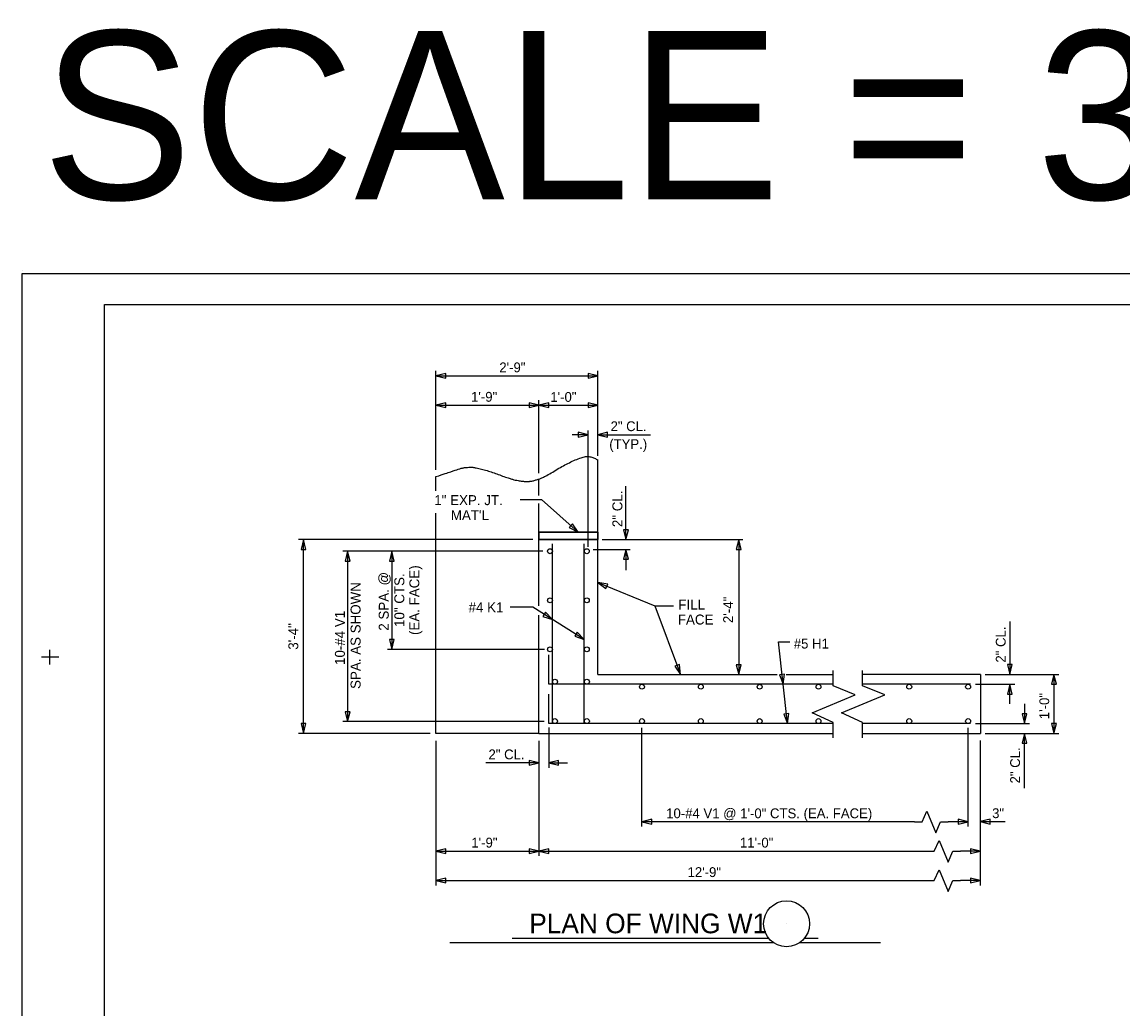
# Model space of a CAD drawing. Extents: x -41 to 251, y -169 to 237.
# Drawn here: x 0 to 18.71, y -82.14 to -65.38 of the extents above; entities that cross this region are included whole.
import ezdxf

# ---------------------------------------------------------------- set-up
doc = ezdxf.new("R2010")
doc.units = 0
for name, color, linetype in [('Arrowhead Terminators CELL', 7, 'Continuous'), ('Beam Bolsters CELL', 7, 'Continuous'), ('Default', 7, 'Continuous'), ('Dimension Lines', 7, 'Continuous'), ('Mis Object Lines', 7, 'Continuous'), ('Plan Sheet CELL', 7, 'Continuous'), ('Plot Shape CELL', 7, 'Continuous'), ('Rebar K Bar Lines', 7, 'Continuous'), ('Rebar Lines', 7, 'Continuous'), ('Sub End Bent Cap Lines CELL', 7, 'Continuous'), ('Text', 7, 'Continuous'), ('Title Text', 7, 'Continuous'), ('User Information Notes CELL', 7, 'Continuous')]:
    doc.layers.add(name, color=color, linetype=linetype)

# ---------------------------------------------------------------- blocks, each defined once
blk = doc.blocks.new('AH')
at = {"layer": 'Sub End Bent Cap Lines CELL'}
blk.add_lwpolyline([(0, 0), (-1.25, 0.31), (-1.25, -0.31)], close=True, dxfattribs=at)

msp = doc.modelspace()

# ---------------------------------------------------------------- linework, layer by layer
at = {"layer": 'Arrowhead Terminators CELL'}
for points in [[(7.033, -71.387), (7.2, -71.428), (7.2, -71.345)], [(9.783, -71.387), (9.617, -71.345), (9.617, -71.428)], [(7.033, -71.887), (7.2, -71.928), (7.2, -71.845)], [(8.783, -71.887), (8.617, -71.845), (8.617, -71.928)], [(8.783, -71.887), (8.95, -71.928), (8.95, -71.845)], [(9.783, -71.887), (9.617, -71.845), (9.617, -71.928)], [(9.617, -72.387), (9.45, -72.345), (9.45, -72.428)], [(9.783, -72.387), (9.95, -72.428), (9.95, -72.345)], [(9.45, -74.044), (9.354, -73.903), (9.298, -73.965)], [(10.261, -74.169), (10.302, -74.003), (10.219, -74.003)], [(4.783, -74.169), (4.742, -74.336), (4.825, -74.336)], [(12.178, -74.169), (12.136, -74.336), (12.219, -74.336)], [(5.533, -74.367), (5.492, -74.534), (5.575, -74.534)], [(6.283, -74.367), (6.242, -74.534), (6.325, -74.534)], [(10.261, -74.337), (10.219, -74.504), (10.302, -74.504)], [(9.783, -74.901), (9.922, -75.002), (9.953, -74.925)], [(9.013, -75.527), (8.893, -75.404), (8.849, -75.475)], [(9.554, -75.864), (9.435, -75.741), (9.391, -75.811)], [(6.283, -76.034), (6.325, -75.867), (6.242, -75.867)], [(11.19, -76.461), (11.17, -76.291), (11.093, -76.32)], [(12.178, -76.461), (12.219, -76.295), (12.136, -76.295)], [(12.932, -76.628), (12.955, -76.458), (12.872, -76.467)], [(5.533, -77.261), (5.575, -77.095), (5.492, -77.095)], [(13.004, -77.294), (13.028, -77.125), (12.945, -77.134)], [(4.783, -77.462), (4.825, -77.296), (4.742, -77.296)], [(8.783, -77.961), (8.617, -77.92), (8.617, -78.003)], [(8.95, -77.961), (9.116, -78.003), (9.116, -77.92)], [(10.533, -78.963), (10.7, -79.004), (10.7, -78.921)], [(16.075, -78.963), (15.908, -78.921), (15.908, -79.004)], [(16.282, -78.961), (16.448, -79.003), (16.448, -78.92)], [(7.033, -79.461), (7.2, -79.503), (7.2, -79.42)], [(8.783, -79.461), (8.617, -79.42), (8.617, -79.503)], [(8.783, -79.461), (8.95, -79.503), (8.95, -79.42)], [(16.282, -79.461), (16.116, -79.42), (16.116, -79.503)], [(7.033, -79.961), (7.2, -80.003), (7.2, -79.92)], [(16.282, -79.961), (16.116, -79.92), (16.116, -80.003)]]:
    msp.add_lwpolyline(points, close=True, dxfattribs=at)
at = {"layer": 'Beam Bolsters CELL'}
msp.add_lwpolyline([(9.742, -74.044), (9.742, -74.044), (9.742, -74.044), (9.742, -74.044), (9.742, -74.044), (9.742, -74.044)], dxfattribs=at)
at = {"layer": 'Default'}
for points in [[(13.781, -77.536), (13.781, -77.278), (13.424, -77.114), (14.156, -76.808), (13.781, -76.653), (13.781, -76.391)], [(14.283, -77.536), (14.283, -77.278), (13.926, -77.114), (14.658, -76.808), (14.283, -76.653), (14.283, -76.391)], [(15.165, -78.963), (15.294, -78.963), (15.376, -78.784), (15.529, -79.15), (15.606, -78.963), (15.738, -78.963)], [(15.372, -79.461), (15.501, -79.461), (15.583, -79.282), (15.736, -79.649), (15.814, -79.461), (15.945, -79.461)], [(15.372, -79.961), (15.501, -79.961), (15.583, -79.782), (15.736, -80.149), (15.814, -79.961), (15.945, -79.961)]]:
    msp.add_lwpolyline(points, dxfattribs=at)
at = {"layer": 'Dimension Lines'}
for p, q in [((10.261, -74.169), (10.261, -73.26)), ((8.465, -73.487), (8.825, -73.487)), ((8.825, -73.487), (9.45, -74.044)), ((9.785, -74.044), (9.45, -74.044)), ((9.783, -74.044), (9.783, -74.169)), ((9.783, -74.169), (9.785, -74.044)), ((8.677, -74.169), (4.699, -74.169)), ((4.783, -77.462), (4.783, -74.169)), ((9.855, -74.169), (12.25, -74.169)), ((12.178, -74.169), (12.178, -76.461)), ((8.847, -74.367), (5.449, -74.367)), ((5.533, -74.367), (5.533, -77.261)), ((6.283, -74.367), (6.283, -76.034)), ((9.707, -74.337), (10.333, -74.337)), ((10.261, -74.337), (10.261, -74.687)), ((9.783, -74.901), (10.754, -75.294)), ((10.754, -75.294), (11.19, -76.461)), ((10.754, -75.294), (11.069, -75.294)), ((16.783, -75.562), (16.783, -76.461)), ((8.878, -76.034), (6.21, -76.034)), ((16.367, -76.461), (17.617, -76.461)), ((16.367, -76.461), (16.72, -76.461)), ((17.533, -76.461), (17.533, -77.461)), ((16.2, -76.628), (16.867, -76.628)), ((16.783, -76.962), (16.783, -76.628)), ((17.033, -76.96), (17.033, -77.294)), ((8.871, -77.261), (5.449, -77.261)), ((8.95, -77.36), (8.95, -78.044)), ((10.533, -79.046), (10.533, -77.365)), ((16.075, -79.046), (16.075, -77.365)), ((16.2, -77.294), (17.117, -77.294)), ((6.933, -77.461), (4.699, -77.461)), ((7.033, -77.589), (7.033, -80.044)), ((8.783, -77.589), (8.783, -79.544)), ((16.282, -77.58), (16.282, -80.044)), ((16.367, -77.461), (17.617, -77.461)), ((16.367, -77.461), (17.009, -77.461)), ((17.033, -78.394), (17.033, -77.461)), ((8.783, -77.961), (7.883, -77.961)), ((8.95, -77.961), (9.269, -77.961)), ((15.165, -78.963), (10.533, -78.963)), ((16.075, -78.963), (15.738, -78.963)), ((16.282, -78.961), (16.707, -78.961)), ((7.033, -79.461), (8.783, -79.461)), ((8.783, -79.461), (15.372, -79.461)), ((16.282, -79.461), (15.945, -79.461)), ((7.033, -79.961), (15.372, -79.961)), ((16.282, -79.961), (15.945, -79.961))]:
    msp.add_line(p, q, dxfattribs=at)
msp.add_lwpolyline([(9.785, -74.044), (9.783, -74.169), (8.783, -74.169), (8.783, -74.044)], close=True, dxfattribs=at)
for points in [[(9.45, -74.044), (8.783, -74.044), (8.783, -74.169), (9.783, -74.169)], [(9.783, -74.169), (9.785, -74.044), (9.783, -74.044)], [(9.554, -75.864), (8.677, -75.319), (8.295, -75.319)], [(13.004, -77.294), (12.854, -75.908), (13.046, -75.908)]]:
    msp.add_lwpolyline(points, dxfattribs=at)
at = {"layer": 'Mis Object Lines'}
for p, q in [((9.783, -76.461), (9.783, -72.817)), ((7.033, -73.343), (7.033, -73.099)), ((8.783, -73.42), (8.783, -73.139)), ((8.783, -75.296), (8.783, -73.555)), ((7.033, -77.461), (7.033, -73.722)), ((9.783, -74.169), (8.783, -74.169)), ((8.783, -77.461), (8.783, -75.452)), ((9.783, -76.461), (12.828, -76.461)), ((12.983, -76.461), (13.781, -76.461)), ((16.283, -76.461), (14.283, -76.461)), ((8.783, -77.461), (7.033, -77.461)), ((8.783, -77.461), (13.781, -77.461)), ((14.283, -77.461), (16.283, -77.461))]:
    msp.add_line(p, q, dxfattribs=at)
msp.add_lwpolyline([(16.283, -76.461), (16.283, -77.461)], dxfattribs=at)
msp.add_open_spline([(7.033, -73.099), (7.165, -73.056), (7.296, -73.012), (7.428, -72.969), (7.45, -72.961), (7.473, -72.956), (7.497, -72.951), (7.52, -72.946), (7.544, -72.944), (7.567, -72.943), (7.614, -72.94), (7.662, -72.94), (7.709, -72.95), (7.807, -72.97), (7.901, -72.997), (7.996, -73.028), (8.093, -73.06), (8.188, -73.1), (8.285, -73.13), (8.333, -73.145), (8.381, -73.158), (8.43, -73.167), (8.465, -73.174), (8.501, -73.178), (8.537, -73.181), (8.549, -73.182), (8.561, -73.182), (8.573, -73.182), (8.585, -73.182), (8.598, -73.182), (8.611, -73.181), (8.624, -73.18), (8.637, -73.178), (8.65, -73.176), (8.677, -73.172), (8.703, -73.166), (8.728, -73.158), (8.783, -73.141), (8.835, -73.12), (8.886, -73.094), (8.994, -73.04), (9.094, -72.972), (9.201, -72.915), (9.299, -72.862), (9.4, -72.815), (9.504, -72.778), (9.57, -72.754), (9.65, -72.757), (9.716, -72.783), (9.74, -72.793), (9.762, -72.803), (9.783, -72.817)], degree=3, dxfattribs=at)
at = {"layer": 'Plan Sheet CELL'}
for p, q in [((0, -69.65), (0, -69.65)), ((1.402, -70.174), (43.962, -70.174)), ((1.402, -98.104), (1.402, -70.174)), ((0.475, -76.292), (0.475, -76.04)), ((0.333, -76.159), (0.626, -76.159))]:
    msp.add_line(p, q, dxfattribs=at)
at = {"layer": 'Plot Shape CELL'}
msp.add_lwpolyline([(0, -69.65), (43.974, -69.65), (43.974, -98.91), (0, -98.91)], close=True, dxfattribs=at)
at = {"layer": 'Rebar K Bar Lines'}
for p, q in [((9.013, -77.294), (9.013, -74.243)), ((9.554, -77.294), (9.554, -74.243))]:
    msp.add_line(p, q, dxfattribs=at)
at = {"layer": 'Rebar Lines'}
for p, q in [((8.95, -76.628), (8.95, -76.128)), ((13.781, -76.628), (8.95, -76.628)), ((16.115, -76.628), (14.283, -76.628)), ((8.95, -77.294), (8.95, -76.794)), ((13.781, -77.294), (8.95, -77.294)), ((16.115, -77.294), (14.283, -77.294))]:
    msp.add_line(p, q, dxfattribs=at)
for centre in [(8.971, -74.367), (9.596, -74.367), (8.971, -75.201), (9.596, -75.201), (8.971, -76.034), (9.596, -76.034), (9.055, -76.584), (9.598, -76.584), (10.533, -76.669), (11.533, -76.669), (12.533, -76.669), (13.533, -76.669), (15.075, -76.669), (16.075, -76.669), (9.055, -77.253), (9.598, -77.253), (10.533, -77.253), (11.533, -77.253), (12.533, -77.253), (13.533, -77.253), (15.075, -77.253), (16.075, -77.253)]:
    msp.add_circle(centre, 0.0417, dxfattribs=at)
at = {"layer": 'Text'}
for p, q in [((7.033, -72.986), (7.033, -71.303)), ((7.033, -71.387), (9.783, -71.387)), ((9.783, -72.745), (9.783, -71.303)), ((8.783, -73.043), (8.783, -71.803)), ((7.033, -71.887), (8.783, -71.887)), ((8.783, -71.887), (9.783, -71.887)), ((9.617, -72.387), (9.346, -72.387)), ((9.617, -74.295), (9.617, -72.314)), ((9.783, -72.387), (10.676, -72.387))]:
    msp.add_line(p, q, dxfattribs=at)
at = {"layer": 'Title Text'}
for p, q in [((8.33, -80.941), (12.687, -80.941)), ((13.294, -80.941), (13.526, -80.941)), ((7.268, -81.015), (12.766, -81.015)), ((13.215, -81.015), (14.588, -81.015))]:
    msp.add_line(p, q, dxfattribs=at)
for centre, radius in [((12.99, -80.696), 0.39), ((12.996, -80.69), 0.000000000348)]:
    msp.add_circle(centre, radius, dxfattribs=at)
at = {"layer": 'User Information Notes CELL'}
for p, q in [((0, -69.599), (0, -69.599)), ((1.402, -70.174), (1.402, -70.174))]:
    msp.add_line(p, q, dxfattribs=at)

# ---------------------------------------------------------------- block references
at = {"layer": 'Arrowhead Terminators CELL', "xscale": 0.1336, "yscale": 0.1336}
for p, rotation in [((16.783, -76.461), -90), ((17.533, -76.461), 90), ((16.783, -76.628), 90), ((17.033, -77.294), -90), ((17.533, -77.461), -90), ((17.033, -77.461), 90)]:
    msp.add_blockref('AH', p, dxfattribs=dict(at, rotation=rotation))

# ---------------------------------------------------------------- texts
at = {"layer": 'Text'}
for s, height, p in [('SCALE = 3/4"', 2.86, (0.339, -68.389)), ('2\'-9"', 0.1667, (8.11, -71.327)), ('1\'-9"', 0.1667, (7.63, -71.827)), ('1\'-0"', 0.1667, (8.977, -71.83)), ('2" CL.', 0.1667, (10, -72.327))]:
    msp.add_text(s, height=height, dxfattribs=at).set_placement(p)
for s, height, rotation, p in [('(TYP.)', 0.1667, 360, (9.978, -72.63)), ('1" EXP. JT.', 0.16954, 360, (7.005, -73.584)), ('2" CL.', 0.1695, 90, (10.201, -73.957)), ("MAT'L", 0.1695, 360, (7.286, -73.839)), ('(EA. FACE)', 0.1695, 90, (6.751, -75.79)), ('2 SPA. @', 0.1695, 90, (6.231, -75.717)), ('10" CTS.', 0.1695, 90, (6.496, -75.654)), ('SPA. AS SHOWN', 0.16954, 90, (5.752, -76.706)), ('FILL', 0.1695, 360, (11.152, -75.358)), ('2\'-4"', 0.1695, 90, (12.083, -75.589)), ('#4 K1', 0.1695, 360, (7.588, -75.405)), ('10-#4 V1', 0.1695, 90, (5.486, -76.299)), ('FACE', 0.1695, 360, (11.143, -75.612)), ('3\'-4"', 0.1695, 90, (4.694, -76.04)), ('2" CL.', 0.167, 90, (16.713, -76.259)), ('#5 H1', 0.167, 360, (13.113, -76.02)), ('1\'-0"', 0.167, 90, (17.453, -77.22)), ('2" CL. ', 0.167, 360, (7.926, -77.902)), ('2" CL.', 0.167, 90, (16.957, -78.312)), ('10-#4 V1 @ 1\'-0" CTS. (EA. FACE)', 0.167, 360, (10.945, -78.903)), ('3"', 0.167, 360, (16.483, -78.901)), ('1\'-9"', 0.167, 360, (7.634, -79.401)), ('11\'-0"', 0.167, 360, (12.197, -79.401)), ('12\'-9"', 0.167, 360, (11.308, -79.902))]:
    msp.add_text(s, height=height, rotation=rotation, dxfattribs=at).set_placement(p)
at = {"layer": 'Title Text'}
msp.add_text('PLAN OF WING W1', height=0.33388, dxfattribs=at).set_placement((8.618, -80.857))

doc.saveas('drawing.dxf')
